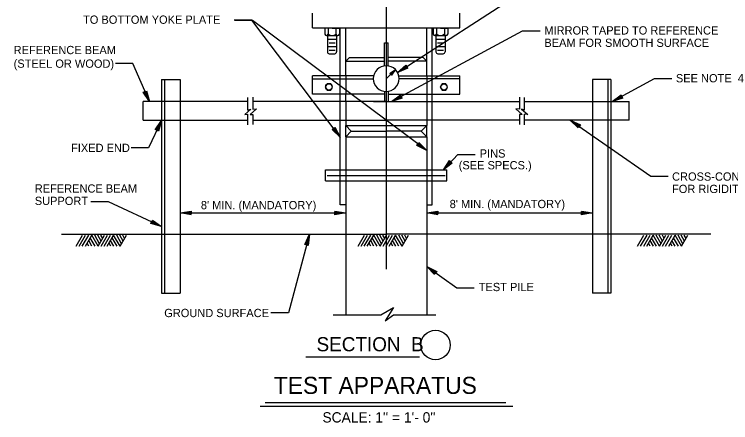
# Model space of a CAD drawing. Extents: x 22369.6 to 22413.6, y 22369.6 to 22403.6.
# Drawn here: x 22389.03 to 22401.19, y 22386.92 to 22393.85 of the extents above; entities that cross this region are included whole.
import ezdxf

# ---------------------------------------------------------------- set-up
doc = ezdxf.new("R2010")
doc.units = 0
for name, color, linetype in [('Level 1', 7, 'Continuous'), ('Level 10', 7, 'Continuous'), ('Level 2', 7, 'Continuous'), ('Level 3', 7, 'Continuous'), ('Level 4', 7, 'Continuous'), ('Level 7', 7, 'Continuous')]:
    doc.layers.add(name, color=color, linetype=linetype)

msp = doc.modelspace()

# ---------------------------------------------------------------- linework, layer by layer
at = {"layer": 'Level 1'}
for p, q in [((22395.344, 22400.675), (22395.344, 22389.526)), ((22394.425, 22393.613), (22394.3, 22393.613)), ((22394.3, 22393.613), (22394.3, 22393.511)), ((22394.358, 22393.613), (22394.358, 22393.511)), ((22394.425, 22393.613), (22394.55, 22393.613)), ((22394.491, 22393.613), (22394.491, 22393.511)), ((22394.55, 22393.613), (22394.55, 22393.511)), ((22396.264, 22393.614), (22396.139, 22393.614)), ((22396.139, 22393.614), (22396.139, 22393.513)), ((22396.198, 22393.614), (22396.198, 22393.513)), ((22396.264, 22393.614), (22396.389, 22393.614)), ((22396.331, 22393.614), (22396.331, 22393.513)), ((22396.389, 22393.614), (22396.389, 22393.513)), ((22394.329, 22393.488), (22394.52, 22393.488)), ((22394.346, 22393.429), (22394.5, 22393.429)), ((22396.168, 22393.489), (22396.36, 22393.489)), ((22396.188, 22393.429), (22396.344, 22393.429)), ((22394.346, 22393.304), (22394.5, 22393.304)), ((22394.373, 22393.367), (22394.475, 22393.367)), ((22396.188, 22393.304), (22396.344, 22393.304)), ((22396.216, 22393.367), (22396.319, 22393.367)), ((22394.373, 22393.242), (22394.475, 22393.242)), ((22396.216, 22393.242), (22396.319, 22393.242)), ((22394.656, 22393.054), (22395.312, 22393.054)), ((22396.031, 22393.054), (22395.375, 22393.054)), ((22395.405, 22392.843), (22395.497, 22392.909)), ((22395.497, 22392.909), (22395.418, 22392.829)), ((22395.497, 22392.909), (22395.431, 22392.816)), ((22395.405, 22392.843), (22395.431, 22392.816)), ((22395.409, 22392.842), (22395.418, 22392.832)), ((22395.485, 22392.898), (22395.41, 22392.844)), ((22395.41, 22392.844), (22395.419, 22392.835)), ((22395.469, 22392.884), (22395.414, 22392.844)), ((22395.414, 22392.844), (22395.419, 22392.839)), ((22395.445, 22392.864), (22395.417, 22392.844)), ((22395.417, 22392.844), (22395.419, 22392.842)), ((22395.418, 22392.832), (22395.485, 22392.898)), ((22395.419, 22392.835), (22395.469, 22392.884)), ((22395.419, 22392.839), (22395.445, 22392.864)), ((22395.419, 22392.842), (22395.427, 22392.849)), ((22395.421, 22392.83), (22395.431, 22392.819)), ((22395.487, 22392.896), (22395.422, 22392.831)), ((22395.422, 22392.831), (22395.431, 22392.823)), ((22395.473, 22392.88), (22395.426, 22392.831)), ((22395.426, 22392.831), (22395.431, 22392.826)), ((22395.453, 22392.856), (22395.429, 22392.832)), ((22395.429, 22392.832), (22395.431, 22392.83)), ((22395.431, 22392.819), (22395.487, 22392.896)), ((22395.431, 22392.823), (22395.473, 22392.88)), ((22395.431, 22392.826), (22395.453, 22392.856)), ((22395.431, 22392.83), (22395.438, 22392.838)), ((22395.537, 22392.86), (22395.537, 22392.86)), ((22395.581, 22392.888), (22395.581, 22392.888)), ((22394.339, 22392.672), (22394.308, 22392.618)), ((22394.402, 22392.672), (22394.339, 22392.672)), ((22394.433, 22392.618), (22394.402, 22392.672)), ((22396.293, 22392.669), (22396.262, 22392.615)), ((22396.356, 22392.669), (22396.293, 22392.669)), ((22396.387, 22392.615), (22396.356, 22392.669)), ((22394.308, 22392.618), (22394.339, 22392.564)), ((22394.339, 22392.564), (22394.402, 22392.564)), ((22394.402, 22392.564), (22394.433, 22392.618)), ((22396.262, 22392.615), (22396.293, 22392.561)), ((22396.293, 22392.561), (22396.356, 22392.561)), ((22396.356, 22392.561), (22396.387, 22392.615)), ((22391.301, 22392.414), (22391.301, 22392.414)), ((22392.993, 22392.225), (22392.993, 22392.435)), ((22393.081, 22392.445), (22393.081, 22392.242)), ((22397.606, 22392.445), (22397.606, 22392.242)), ((22397.694, 22392.225), (22397.694, 22392.435)), ((22391.322, 22392.367), (22391.322, 22392.367)), ((22395.435, 22392.367), (22395.435, 22392.367)), ((22395.481, 22392.391), (22395.481, 22392.391)), ((22399.182, 22392.367), (22399.182, 22392.367)), ((22399.227, 22392.392), (22399.227, 22392.392)), ((22393.044, 22392.237), (22392.941, 22392.151)), ((22392.993, 22392.225), (22393.044, 22392.237)), ((22393.144, 22392.248), (22393.036, 22392.151)), ((22393.081, 22392.242), (22393.144, 22392.248)), ((22397.543, 22392.248), (22397.651, 22392.151)), ((22397.606, 22392.242), (22397.543, 22392.248)), ((22397.694, 22392.225), (22397.643, 22392.237)), ((22397.643, 22392.237), (22397.747, 22392.151)), ((22392.941, 22392.151), (22392.993, 22392.153)), ((22392.993, 22391.972), (22392.993, 22392.153)), ((22393.036, 22392.151), (22393.081, 22392.149)), ((22393.081, 22392.149), (22393.081, 22391.978)), ((22397.651, 22392.151), (22397.606, 22392.149)), ((22397.606, 22392.149), (22397.606, 22391.978)), ((22397.694, 22391.972), (22397.694, 22392.153)), ((22397.747, 22392.151), (22397.694, 22392.153)), ((22398.468, 22392.054), (22398.468, 22392.054)), ((22391.509, 22392), (22391.509, 22392)), ((22391.531, 22392.046), (22391.531, 22392.046)), ((22394.656, 22391.961), (22396.031, 22391.961)), ((22398.511, 22392.025), (22398.511, 22392.025)), ((22394.531, 22391.807), (22394.531, 22391.807)), ((22394.562, 22391.766), (22394.562, 22391.766)), ((22394.656, 22391.773), (22396.031, 22391.773)), ((22395.989, 22391.57), (22395.989, 22391.57)), ((22396.031, 22391.539), (22396.031, 22391.539)), ((22396.314, 22391.211), (22396.314, 22391.211)), ((22396.35, 22391.248), (22396.35, 22391.248)), ((22394.343, 22391.117), (22396.346, 22391.117)), ((22391.846, 22390.479), (22394.656, 22390.479)), ((22391.846, 22390.479), (22391.846, 22390.479)), ((22391.898, 22390.479), (22391.898, 22390.479)), ((22394.606, 22390.479), (22394.606, 22390.479)), ((22394.658, 22390.479), (22394.658, 22390.479)), ((22396.033, 22390.479), (22398.844, 22390.479)), ((22396.033, 22390.479), (22396.033, 22390.479)), ((22396.085, 22390.479), (22396.085, 22390.479)), ((22398.794, 22390.479), (22398.794, 22390.479)), ((22398.846, 22390.479), (22398.846, 22390.479)), ((22391.484, 22390.272), (22391.484, 22390.272)), ((22391.531, 22390.25), (22391.531, 22390.25)), ((22394.039, 22390.117), (22394.039, 22390.117)), ((22390.08, 22389.913), (22390.188, 22390.1)), ((22390.132, 22389.913), (22390.24, 22390.1)), ((22390.184, 22389.913), (22390.292, 22390.1)), ((22390.236, 22389.913), (22390.344, 22390.1)), ((22390.348, 22389.913), (22390.292, 22390.01)), ((22390.4, 22389.913), (22390.318, 22390.055)), ((22390.452, 22389.913), (22390.344, 22390.1)), ((22390.478, 22389.958), (22390.396, 22390.1)), ((22390.504, 22390.003), (22390.448, 22390.1)), ((22390.452, 22389.913), (22390.56, 22390.1)), ((22390.53, 22390.048), (22390.5, 22390.1)), ((22390.504, 22389.913), (22390.613, 22390.1)), ((22390.556, 22389.913), (22390.664, 22390.1)), ((22390.608, 22389.913), (22390.716, 22390.1)), ((22390.721, 22389.913), (22390.664, 22390.01)), ((22390.773, 22389.913), (22390.69, 22390.055)), ((22390.825, 22389.913), (22390.716, 22390.1)), ((22390.851, 22389.958), (22390.768, 22390.1)), ((22390.877, 22390.003), (22390.82, 22390.1)), ((22390.825, 22389.913), (22390.933, 22390.1)), ((22390.903, 22390.048), (22390.872, 22390.1)), ((22394.025, 22390.067), (22394.025, 22390.067)), ((22394.868, 22389.913), (22394.976, 22390.1)), ((22394.92, 22389.913), (22395.028, 22390.1)), ((22394.972, 22389.913), (22395.08, 22390.1)), ((22395.023, 22389.913), (22395.132, 22390.1)), ((22395.136, 22389.913), (22395.08, 22390.01)), ((22395.188, 22389.913), (22395.106, 22390.055)), ((22395.24, 22389.913), (22395.132, 22390.1)), ((22395.266, 22389.958), (22395.184, 22390.1)), ((22395.292, 22390.003), (22395.236, 22390.1)), ((22395.24, 22389.913), (22395.348, 22390.1)), ((22395.318, 22390.048), (22395.288, 22390.1)), ((22395.292, 22389.913), (22395.4, 22390.1)), ((22395.344, 22389.913), (22395.452, 22390.1)), ((22395.396, 22389.913), (22395.504, 22390.1)), ((22395.508, 22389.913), (22395.452, 22390.01)), ((22395.56, 22389.913), (22395.478, 22390.055)), ((22395.612, 22389.913), (22395.504, 22390.1)), ((22395.638, 22389.958), (22395.556, 22390.1)), ((22395.664, 22390.003), (22395.608, 22390.1)), ((22395.612, 22389.913), (22395.721, 22390.1)), ((22395.69, 22390.048), (22395.66, 22390.1)), ((22399.611, 22389.913), (22399.72, 22390.1)), ((22399.663, 22389.913), (22399.772, 22390.1)), ((22399.715, 22389.913), (22399.824, 22390.1)), ((22399.767, 22389.913), (22399.876, 22390.1)), ((22399.88, 22389.913), (22399.824, 22390.01)), ((22399.932, 22389.913), (22399.85, 22390.055)), ((22399.984, 22389.913), (22399.876, 22390.1)), ((22400.01, 22389.958), (22399.928, 22390.1)), ((22400.036, 22390.003), (22399.98, 22390.1)), ((22399.984, 22389.913), (22400.092, 22390.1)), ((22400.062, 22390.048), (22400.032, 22390.1)), ((22400.036, 22389.913), (22400.144, 22390.1)), ((22400.088, 22389.913), (22400.196, 22390.1)), ((22400.14, 22389.913), (22400.248, 22390.1)), ((22400.252, 22389.913), (22400.196, 22390.01)), ((22400.304, 22389.913), (22400.222, 22390.055)), ((22400.356, 22389.913), (22400.248, 22390.1)), ((22400.382, 22389.958), (22400.3, 22390.1)), ((22400.408, 22390.003), (22400.352, 22390.1)), ((22400.356, 22389.913), (22400.465, 22390.1)), ((22400.434, 22390.048), (22400.404, 22390.1)), ((22390.296, 22389.913), (22390.266, 22389.965)), ((22390.669, 22389.913), (22390.639, 22389.965)), ((22395.084, 22389.913), (22395.054, 22389.965)), ((22395.457, 22389.913), (22395.426, 22389.965)), ((22399.828, 22389.913), (22399.798, 22389.965)), ((22400.2, 22389.913), (22400.17, 22389.965)), ((22396.031, 22389.57), (22396.031, 22389.57)), ((22396.073, 22389.54), (22396.073, 22389.54))]:
    msp.add_line(p, q, dxfattribs=at)
for points in [[(22395.537, 22392.86), (22397.693, 22394.257), (22397.989, 22394.257)], [(22394.562, 22391.766), (22393.06, 22393.75), (22392.764, 22393.75)], [(22396.031, 22391.539), (22393.071, 22393.745), (22392.775, 22393.745)], [(22395.435, 22392.367), (22397.659, 22393.567), (22397.955, 22393.567)], [(22391.322, 22392.367), (22391.042, 22393.013), (22390.745, 22393.013)], [(22395.711, 22392.935), (22395.537, 22392.86), (22395.677, 22392.987), (22395.706, 22392.943), (22395.581, 22392.888), (22395.676, 22392.975), (22395.694, 22392.946), (22395.623, 22392.915), (22395.675, 22392.962), (22395.682, 22392.95), (22395.666, 22392.943)], [(22399.182, 22392.367), (22399.897, 22392.758), (22400.194, 22392.758)], [(22391.276, 22392.551), (22391.322, 22392.367), (22391.219, 22392.526), (22391.268, 22392.547), (22391.301, 22392.414), (22391.231, 22392.523), (22391.262, 22392.536), (22391.281, 22392.46), (22391.244, 22392.519), (22391.257, 22392.525), (22391.261, 22392.508)], [(22395.614, 22392.428), (22395.435, 22392.367), (22395.585, 22392.483), (22395.61, 22392.436), (22395.481, 22392.391), (22395.582, 22392.47), (22395.599, 22392.44), (22395.525, 22392.415), (22395.58, 22392.458), (22395.587, 22392.445), (22395.57, 22392.44)], [(22399.361, 22392.429), (22399.182, 22392.367), (22399.331, 22392.484), (22399.356, 22392.437), (22399.227, 22392.392), (22399.329, 22392.471), (22399.345, 22392.441), (22399.271, 22392.416), (22399.326, 22392.458), (22399.333, 22392.446), (22399.317, 22392.441)], [(22398.468, 22392.054), (22399.834, 22391.105), (22400.13, 22391.105)], [(22398.604, 22391.922), (22398.468, 22392.054), (22398.64, 22391.973), (22398.609, 22391.929), (22398.511, 22392.025), (22398.627, 22391.969), (22398.608, 22391.941), (22398.552, 22391.996), (22398.615, 22391.966), (22398.607, 22391.954), (22398.595, 22391.966)], [(22391.531, 22392.046), (22391.309, 22391.581), (22391.013, 22391.581)], [(22391.423, 22391.891), (22391.531, 22392.046), (22391.479, 22391.864), (22391.431, 22391.887), (22391.509, 22392), (22391.473, 22391.876), (22391.442, 22391.89), (22391.487, 22391.954), (22391.467, 22391.887), (22391.455, 22391.893), (22391.465, 22391.907)], [(22394.474, 22391.934), (22394.562, 22391.766), (22394.425, 22391.896), (22394.467, 22391.928), (22394.531, 22391.807), (22394.437, 22391.896), (22394.465, 22391.916), (22394.501, 22391.847), (22394.45, 22391.895), (22394.461, 22391.904), (22394.469, 22391.889)], [(22395.9, 22391.676), (22396.031, 22391.539), (22395.863, 22391.626), (22395.894, 22391.669), (22395.989, 22391.57), (22395.875, 22391.629), (22395.895, 22391.657), (22395.949, 22391.6), (22395.887, 22391.633), (22395.896, 22391.644), (22395.908, 22391.631)], [(22396.314, 22391.211), (22396.56, 22391.472), (22396.856, 22391.472)], [(22396.465, 22391.326), (22396.314, 22391.211), (22396.42, 22391.368), (22396.458, 22391.332), (22396.35, 22391.248), (22396.421, 22391.355), (22396.446, 22391.332), (22396.384, 22391.285), (22396.423, 22391.343), (22396.434, 22391.333), (22396.42, 22391.323)], [(22391.531, 22390.25), (22390.626, 22390.668), (22390.33, 22390.668)], [(22392.033, 22390.448), (22391.846, 22390.479), (22392.033, 22390.51), (22392.033, 22390.457), (22391.898, 22390.479), (22392.025, 22390.5), (22392.025, 22390.466), (22391.948, 22390.479), (22392.017, 22390.49), (22392.017, 22390.476), (22392, 22390.479)], [(22394.471, 22390.51), (22394.658, 22390.479), (22394.471, 22390.448), (22394.471, 22390.501), (22394.606, 22390.479), (22394.479, 22390.458), (22394.479, 22390.492), (22394.556, 22390.479), (22394.487, 22390.468), (22394.487, 22390.482), (22394.504, 22390.479)], [(22396.22, 22390.448), (22396.033, 22390.479), (22396.22, 22390.51), (22396.22, 22390.457), (22396.085, 22390.479), (22396.212, 22390.5), (22396.212, 22390.466), (22396.135, 22390.479), (22396.204, 22390.49), (22396.204, 22390.476), (22396.187, 22390.479)], [(22398.659, 22390.51), (22398.846, 22390.479), (22398.659, 22390.448), (22398.659, 22390.501), (22398.794, 22390.479), (22398.667, 22390.458), (22398.667, 22390.492), (22398.744, 22390.479), (22398.675, 22390.468), (22398.675, 22390.482), (22398.692, 22390.479)], [(22391.374, 22390.357), (22391.531, 22390.25), (22391.348, 22390.301), (22391.37, 22390.349), (22391.484, 22390.272), (22391.36, 22390.306), (22391.374, 22390.337), (22391.438, 22390.293), (22391.371, 22390.312), (22391.377, 22390.325), (22391.391, 22390.315)], [(22394.039, 22390.117), (22393.682, 22388.783), (22393.385, 22388.783)], [(22393.961, 22389.944), (22394.039, 22390.117), (22394.02, 22389.928), (22393.969, 22389.942), (22394.025, 22390.067), (22394.013, 22389.938), (22393.98, 22389.947), (22394.012, 22390.018), (22394.005, 22389.949), (22393.992, 22389.952), (22393.999, 22389.968)], [(22396.031, 22389.57), (22396.54, 22389.21), (22396.836, 22389.21)], [(22396.166, 22389.436), (22396.031, 22389.57), (22396.202, 22389.487), (22396.171, 22389.444), (22396.073, 22389.54), (22396.189, 22389.483), (22396.17, 22389.456), (22396.114, 22389.511), (22396.177, 22389.48), (22396.169, 22389.468), (22396.157, 22389.481)]]:
    msp.add_lwpolyline(points, dxfattribs=at)
for centre in [(22394.37, 22392.618), (22396.325, 22392.615)]:
    msp.add_circle(centre, 0.0537, dxfattribs=at)
for centre, radius, start, end in [((22394.329, 22393.518), 0.03, 192.6156, 347.3843), ((22394.425, 22393.594), 0.106, 231.0814, 308.9186), ((22394.521, 22393.518), 0.03, 192.7052, 347.2948), ((22396.169, 22393.519), 0.03, 192.5166, 347.4834), ((22396.264, 22393.595), 0.106, 231.1143, 308.8857), ((22396.36, 22393.519), 0.03, 192.5166, 347.4834)]:
    msp.add_arc(centre, radius, start, end, dxfattribs=at)
at = {"layer": 'Level 10'}
for p, q in [((22393.978, 22388.041), (22395.909, 22388.041)), ((22393.201, 22387.204), (22397.494, 22387.204)), ((22393.29, 22387.266), (22397.376, 22387.266))]:
    msp.add_line(p, q, dxfattribs=at)
at = {"layer": 'Level 2'}
for p, q in [((22394.346, 22393.485), (22394.346, 22393.211)), ((22394.5, 22393.486), (22394.5, 22393.211)), ((22396.188, 22393.487), (22396.188, 22393.211)), ((22396.344, 22393.488), (22396.344, 22393.211)), ((22395.312, 22392.974), (22395.312, 22393.367)), ((22395.312, 22393.367), (22395.375, 22393.367)), ((22395.375, 22392.974), (22395.375, 22393.367)), ((22394.377, 22393.179), (22394.469, 22393.179)), ((22396.219, 22393.179), (22396.313, 22393.179)), ((22395.344, 22392.757), (22395.487, 22392.901)), ((22394.562, 22392.492), (22394.562, 22392.804)), ((22394.656, 22392.804), (22394.656, 22392.492)), ((22396.031, 22392.804), (22396.031, 22392.492)), ((22396.125, 22392.492), (22396.125, 22392.804)), ((22391.578, 22392.742), (22391.578, 22390.117)), ((22394.094, 22392.757), (22395.125, 22392.757)), ((22396.594, 22392.757), (22395.562, 22392.757)), ((22399.109, 22392.742), (22399.109, 22390.117)), ((22395.313, 22392.538), (22395.313, 22392.367)), ((22395.377, 22392.537), (22395.377, 22392.367)), ((22391.844, 22392.367), (22391.531, 22392.367)), ((22394.562, 22392.054), (22394.562, 22392.367)), ((22394.656, 22392.367), (22394.656, 22392.054)), ((22396.031, 22392.367), (22396.031, 22392.054)), ((22396.125, 22392.054), (22396.125, 22392.367)), ((22398.844, 22392.367), (22399.156, 22392.367)), ((22391.531, 22392.054), (22391.844, 22392.054)), ((22399.156, 22392.054), (22398.844, 22392.054)), ((22394.562, 22391.211), (22396.125, 22391.211)), ((22394.562, 22391.023), (22396.125, 22391.023)), ((22389.83, 22390.117), (22395.344, 22390.117)), ((22391.531, 22390.117), (22391.531, 22389.117)), ((22391.578, 22390.117), (22391.578, 22389.117)), ((22391.844, 22390.117), (22391.844, 22389.117)), ((22394.656, 22390.117), (22394.656, 22388.753)), ((22400.857, 22390.117), (22395.344, 22390.117)), ((22396.031, 22390.117), (22396.031, 22388.753)), ((22398.844, 22390.117), (22398.844, 22389.117)), ((22399.109, 22390.117), (22399.109, 22389.117)), ((22399.156, 22390.117), (22399.156, 22389.117)), ((22391.531, 22389.117), (22391.844, 22389.117)), ((22399.156, 22389.117), (22398.844, 22389.117)), ((22395.254, 22388.753), (22395.468, 22388.877)), ((22395.468, 22388.877), (22395.324, 22388.647)), ((22394.441, 22388.753), (22395.254, 22388.753)), ((22395.324, 22388.647), (22395.465, 22388.753)), ((22395.465, 22388.753), (22396.188, 22388.753))]:
    msp.add_line(p, q, dxfattribs=at)
for centre, radius, start, end in [((22394.377, 22393.211), 0.0313, 179.9906, 270.0094), ((22394.469, 22393.21), 0.0311, 269.8556, 0.3354), ((22396.219, 22393.211), 0.0314, 180.121, 269.688), ((22396.313, 22393.21), 0.0311, 269.8556, 0.3354)]:
    msp.add_arc(centre, radius, start, end, dxfattribs=at)
at = {"layer": 'Level 3'}
msp.add_line((22395.129, 22392.372), (22395.562, 22392.372), dxfattribs=at)
msp.add_circle((22396.181, 22388.239), 0.25, dxfattribs=at)
at = {"layer": 'Level 7'}
for p, q in [((22394.094, 22393.617), (22394.094, 22393.867)), ((22396.594, 22393.617), (22396.594, 22393.867)), ((22394.094, 22393.617), (22396.594, 22393.617)), ((22394.562, 22392.804), (22394.562, 22393.617)), ((22394.656, 22392.804), (22394.656, 22393.617)), ((22396.031, 22392.804), (22396.031, 22393.617)), ((22396.125, 22392.804), (22396.125, 22393.617)), ((22394.656, 22393.054), (22394.719, 22393.117)), ((22394.719, 22393.117), (22395.312, 22393.117)), ((22395.969, 22393.117), (22395.375, 22393.117)), ((22396.031, 22393.054), (22395.969, 22393.117)), ((22395.13, 22392.804), (22394.094, 22392.804)), ((22394.094, 22392.492), (22394.094, 22392.804)), ((22395.557, 22392.804), (22396.594, 22392.804)), ((22396.594, 22392.492), (22396.594, 22392.804)), ((22391.531, 22392.742), (22391.844, 22392.742)), ((22391.531, 22392.742), (22391.531, 22390.117)), ((22391.844, 22392.742), (22391.844, 22390.117)), ((22399.156, 22392.742), (22398.844, 22392.742)), ((22398.844, 22392.742), (22398.844, 22390.117)), ((22399.156, 22392.742), (22399.156, 22390.117)), ((22395.312, 22392.492), (22394.094, 22392.492)), ((22394.562, 22392.367), (22394.562, 22392.492)), ((22394.656, 22392.367), (22394.656, 22392.492)), ((22395.375, 22392.492), (22396.594, 22392.492)), ((22396.031, 22392.492), (22396.031, 22392.367)), ((22396.125, 22392.367), (22396.125, 22392.492)), ((22391.219, 22392.054), (22391.219, 22392.367)), ((22391.531, 22392.367), (22391.219, 22392.367)), ((22392.993, 22392.367), (22391.844, 22392.367)), ((22395.344, 22392.367), (22393.081, 22392.367)), ((22395.344, 22392.367), (22397.606, 22392.367)), ((22397.694, 22392.367), (22398.844, 22392.367)), ((22399.156, 22392.367), (22399.469, 22392.367)), ((22399.469, 22392.054), (22399.469, 22392.367)), ((22391.219, 22392.054), (22391.531, 22392.054)), ((22391.844, 22392.054), (22392.993, 22392.054)), ((22393.081, 22392.054), (22395.344, 22392.054)), ((22394.562, 22390.617), (22394.562, 22392.054)), ((22394.656, 22392.054), (22394.656, 22391.961)), ((22397.606, 22392.054), (22395.344, 22392.054)), ((22396.031, 22392.054), (22396.031, 22391.961)), ((22396.125, 22390.617), (22396.125, 22392.054)), ((22398.844, 22392.054), (22397.694, 22392.054)), ((22399.469, 22392.054), (22399.156, 22392.054)), ((22394.656, 22391.961), (22394.75, 22391.867)), ((22394.656, 22391.773), (22394.656, 22391.961)), ((22396.031, 22391.961), (22395.937, 22391.867)), ((22396.031, 22391.773), (22396.031, 22391.961)), ((22394.656, 22391.773), (22394.75, 22391.867)), ((22394.75, 22391.867), (22395.344, 22391.867)), ((22395.937, 22391.867), (22395.344, 22391.867)), ((22396.031, 22391.773), (22395.937, 22391.867)), ((22394.656, 22391.773), (22394.656, 22390.117)), ((22396.031, 22391.773), (22396.031, 22390.117)), ((22394.312, 22391.211), (22394.562, 22391.211)), ((22394.312, 22391.023), (22394.312, 22391.211)), ((22396.125, 22391.211), (22396.375, 22391.211)), ((22396.375, 22391.023), (22396.375, 22391.211)), ((22394.312, 22391.023), (22394.562, 22391.023)), ((22396.125, 22391.023), (22396.375, 22391.023)), ((22394.656, 22390.617), (22394.562, 22390.617)), ((22396.031, 22390.617), (22396.125, 22390.617))]:
    msp.add_line(p, q, dxfattribs=at)
for centre, start, end in [((22395.344, 22392.757), 90.0166, 179.9562), ((22395.344, 22392.757), 359.9973, 90.0027), ((22395.344, 22392.757), 179.9979, 270.0021), ((22395.343, 22392.758), 270.0438, 359.9834)]:
    msp.add_arc(centre, 0.219, start, end, dxfattribs=at)

# ---------------------------------------------------------------- texts
at = {"layer": 'Level 3'}
for s, height, p in [('SECTION  B', 0.24, (22394.161, 22388.132)), ('TEST APPARATUS', 0.29, (22393.435, 22387.409))]:
    msp.add_text(s, height=height, dxfattribs=at).set_placement(p)
at = {"layer": 'Level 4'}
for s, height, p in [('TO BOTTOM YOKE PLATE', 0.14, (22390.197, 22393.688)), ('MIRROR TAPED TO REFERENCE', 0.14, (22398.029, 22393.506)), ('BEAM FOR SMOOTH SURFACE', 0.14, (22398.029, 22393.296)), ('REFERENCE BEAM', 0.14, (22389.018, 22393.173)), ('(STEEL OR WOOD)', 0.14, (22389.018, 22392.942)), ('SEE NOTE  4', 0.14, (22400.262, 22392.695)), ('FIXED END', 0.14, (22389.993, 22391.513)), ('PINS', 0.14, (22396.931, 22391.418)), ('(SEE SPECS.)', 0.14, (22396.575, 22391.219)), ('CROSS-CONNECTIONS', 0.14, (22400.197, 22391.027)), ('REFERENCE BEAM', 0.14, (22389.377, 22390.824)), ('FOR RIGIDITY', 0.14, (22400.197, 22390.817)), ('SUPPORT', 0.14, (22389.377, 22390.614)), ("8' MIN. (MANDATORY)", 0.14, (22392.197, 22390.542)), ("8' MIN. (MANDATORY)", 0.14, (22396.421, 22390.561)), ('TEST PILE', 0.14, (22396.915, 22389.153)), ('GROUND SURFACE', 0.14, (22391.575, 22388.712)), ("SCALE: 1'' = 1'- 0''", 0.175, (22394.261, 22386.924))]:
    msp.add_text(s, height=height, dxfattribs=at).set_placement(p)

doc.saveas('drawing.dxf')
